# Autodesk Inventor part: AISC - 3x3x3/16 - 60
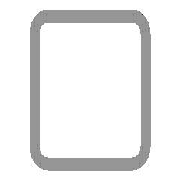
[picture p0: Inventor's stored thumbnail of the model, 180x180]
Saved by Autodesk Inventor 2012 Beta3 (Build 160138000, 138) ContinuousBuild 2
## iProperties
IsCustomPart: 1
Created: 2010-11
Part Number: AISC - 3x3x3/16 - 60
Material: Steel, Mild
Description: Tube
Document SubType Name: Modeling
Standard: ANSI
Designer: Beta-8540w
Standards Organization: ANSI
Language: en-US
Size Designation: 3x3x3/16
Categories: <MemberInstance><Categories><Category DisplayName="Structural Shapes" InternalName="089c4875-fa83-4c05-b084-43b9cc11f5ed" Mnemonic="GRDR"><CategoryParameter Dis
Stock Number: 3x3x3/16
Density: 7.86 g/cm^3
_CCFamilyMember: 9
_CCFamilyDisplayName: ANSI AISC (Square) - Tube
_FrameMemberDoc: Frame Member File
_Version: 15.0.0
_GetPNFromCC: 1
G_L: 60.000 in
G_W: 3.000 in
G_H: 3.000 in
Author: Beta-8540w
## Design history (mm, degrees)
node "Start plane"
node "End plane"
sketch "Sketch"
  geometry: L1 (-38.1, -28.575)-(-38.1, 28.575); L2 (-28.575, 38.1)-(28.575, 38.1); L3 (38.1, 28.575)-(38.1, -28.575); L4 (28.575, -38.1)-(-28.575, -38.1); L5 (-28.575, 33.337)-(28.575, 33.338); L6 (33.338, 28.575)-(33.338, -28.575); L7 (28.575, -33.337)-(-28.575, -33.338); L8 (-33.338, -28.575)-(-33.338, 28.575); L9 (0, 56.102)-(0, -56.102) reference; L10 (-56.102, 0)-(56.102, 0) reference; A1 r 9.525 centre (-28.575, -28.575) between (-38.1, -28.575) and (-28.575, -38.1); A2 r 9.525 centre (-28.575, 28.575) between (-28.575, 38.1) and (-38.1, 28.575); A3 r 9.525 centre (28.575, 28.575) between (38.1, 28.575) and (28.575, 38.1); A4 r 9.525 centre (28.575, -28.575) between (28.575, -38.1) and (38.1, -28.575); A5 r 4.763 centre (-28.575, 28.575) between (-28.575, 33.337) and (-33.338, 28.575); A6 r 4.763 centre (28.575, 28.575) between (33.338, 28.575) and (28.575, 33.338); A7 r 4.763 centre (28.575, -28.575) between (28.575, -33.337) and (33.338, -28.575); A8 r 4.763 centre (-28.575, -28.575) between (-33.338, -28.575) and (-28.575, -33.338)
  constraints: 16 end point, 16 point on circle, 8 centre point, 8 tangent, 4 parallel, 3 equal radius, 2 perpendicular, 7 other
  dimensions: "d10" = 76.2 distance between parallel lines of L2 L4 (= G_H); "d11" = 76.2 distance between parallel lines of L1 L3 (= G_W); "d12" = 4.7625 distance between parallel lines of L3 L6 (= G_T); "d15" = 38.1 distance between parallel lines of L2 L10 (= 0.5 x d10); "d16" = 38.1 distance between parallel lines of L9 L3 (= 0.5 x d11); "d17" = 9.525 radius of A1 (= G_IR)
extrude "Body" new body sketch "Sketch" stored distance "d3" = 1524 (= G_L); taper "d4" = 0 deg
node "Driven Length"
  sketch "Sketch3"
    geometry: L1 (0, 0)-(10, 0) reference
    constraints: 2 end point, 1 horizontal
  workplane "Work Plane3"
  sketch "Sketch4"
    geometry: L1 (-2, 0)-(12, 0) reference; L2 (-2, 1524)-(12, 1524) reference
    dimensions: "d19" = 1524 distance between parallel lines of L1 L2 (derived)
body "Solid1"
other parameters: "G_W" = 76.2 [user parameter; used in 1 equation term], "G_H" = 76.2 [user parameter; used in 1 equation term], "G_T" = 4.7625 [user parameter; used in 1 equation term], "G_IR" = 9.525 [user parameter; used in 1 equation term], "G_L" = 1524 (= d19) [user parameter; used in 1 equation term], "G_OFFSET_START" = 0 [user parameter; used in 1 equation term], "G_OFFSET_END" = 0 [user parameter; used in 1 equation term], "d13" = 0 (computed from G_OFFSET_START), "d14" = 1524 (= G_OFFSET_END + B_L), "B_L" = 1524 [user parameter; used in 1 equation term], "d18" = 90 deg
